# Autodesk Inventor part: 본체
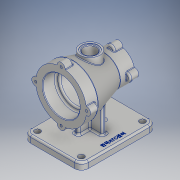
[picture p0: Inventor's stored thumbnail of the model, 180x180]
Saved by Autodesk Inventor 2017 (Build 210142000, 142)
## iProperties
Part Number: 본체
Material: 알루미늄 6061
Document SubType Name: Modeling
Designer: 222
Density: 2.7 g/cm^3
Appearance: 알루미늄 - 평지
Mass: 1029.94 g
Surface Area: 851.12 cm^2
Volume: 381.46 cm^3
Author: 222
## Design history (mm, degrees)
sketch "스케치1"
  geometry: L1 (-50, 0)-(50, 0); L2 (-50, 0)-(-50, 44); L3 (-50, 44)-(-30, 44); L4 (-30, 44)-(25, 27.5); L5 (25, 27.5)-(50, 27.5); L6 (50, 27.5)-(50, 0); 2 further points
  constraints: 12 end point, 2 horizontal, 2 perpendicular, 1 coincident, 1 midpoint, 1 vertical
  dimensions: "d0" = 100 distance of L1.start L1.end; "d1" = 88 diameter of L3 L1; "d2" = 55 diameter of L5 L1; "d3" = 20 distance of L2.end L3.end; "d5" = 25 distance of L4.end L5.end
revolve "회전1" sketch "스케치1" stored, may be unused: angle "d6" = 90 deg
node "작업 평면2"
sketch "스케치2"
  geometry: L1 (65, 50)-(-65, 50); L2 (-65, 50)-(-65, -50); L3 (-65, -50)-(65, -50); L4 (65, -50)-(65, 50); L5 (65, 50)-(-65, -50); L6 (-65, 50)-(65, -50); 1 further point
  constraints: 12 end point, 2 midpoint, 2 parallel, 1 horizontal, 1 perpendicular
  dimensions: "d8" = 130 distance of L2.end L3.end; "d9" = 100 distance of L1.end L2.end
extrude "돌출1" join sketch "스케치2" distance "d10" = 12; taper "d11" = 0 deg
fillet "모깎기1" dims "d12" = 12
sketch "스케치3"
  geometry: A1 r 12 centre (-53, 38) between (-53, 50) and (-65, 38) reference; A2 r 12 centre (53, 38) between (65, 38) and (53, 50) reference; A3 r 12 centre (53, -38) between (53, -50) and (65, -38) reference; A4 r 12 centre (-53, -38) between (-65, -38) and (-53, -50) reference; 1 further point
hole "구멍1" sketch "스케치3" at (-53, 38), (-53, -38), (53, -38), (53, 38) diameter "d13" = 10; stored, may be unused: countersink angle "d17" = 90 deg, drill point angle "d19" = 118 deg; dims "d14" = 6, "d15" = 4, "d16" = 2, "d18" = 8
node "작업 평면3"
sketch "스케치4"
  geometry: C1 r 17 at (0, 0); 1 further point
  constraints: 1 centre point, 1 coincident
  dimensions: "d21" = 34 diameter of C1
extrude "돌출2" join sketch "스케치4" stored distance "d22" = 12; taper "d23" = 0 deg
sketch "스케치11"
  geometry: L1 (-24, -4)-(24, -4); L2 (24, -4)-(24, 4); L3 (24, 4)-(-24, 4); L4 (-24, 4)-(-24, -4); L5 (-24, -4)-(24, 4); L6 (24, -4)-(-24, 4); L7 (-4, -25)-(4, -25); L8 (4, -25)-(4, 25); L9 (4, 25)-(-4, 25); L10 (-4, 25)-(-4, -25); L11 (-4, -25)-(4, 25); L12 (4, -25)-(-4, 25); 1 further point
  constraints: 24 end point, 4 midpoint, 4 parallel, 2 horizontal, 2 perpendicular
  dimensions: "d45" = 8 distance of L1.end L2.end; "d46" = 8 distance of L8.end L9.end; "d47" = 50 distance of L7.end L8.end; "d48" = 48 distance of L2.end L3.end
extrude "돌출8" join sketch "스케치11" stored distance "d49" = 33.5; taper "d50" = 0 deg
sketch "스케치12"
  geometry: C1 r 32 at (0, 0); 1 further point
  constraints: 1 centre point, 1 coincident
  dimensions: "d51" = 64 diameter of C1
extrude "돌출9" cut sketch "스케치12" distance "d52" = 23; taper "d53" = 0 deg
sketch "스케치13"
  geometry: C1 r 26 at (0, 0); 1 further point
  constraints: 1 centre point, 1 coincident
  dimensions: "d54" = 52 diameter of C1
extrude "돌출10" cut sketch "스케치13" distance "d55" = 47; taper "d56" = 0 deg
sketch "스케치14"
  geometry: C1 r 20 at (0, 0); 1 further point
  constraints: 1 centre point, 1 coincident
  dimensions: "d57" = 40 diameter of C1
extrude "돌출11" cut sketch "스케치14" distance "d58" = 30; taper "d59" = 0 deg
chamfer "모따기3" distance "d60" = 1; stored, may be unused: second distance "d61" = 2, angle "d62" = 45 deg
sketch "스케치15"
  geometry: C1 r 14 at (0, 0); 1 further point
  constraints: 1 centre point, 1 coincident
  dimensions: "d63" = 28 diameter of C1
extrude "돌출12" cut sketch "스케치15" distance "d64" = 1; taper "d65" = 0 deg
sketch "스케치16"
  geometry: C1 r 11 at (0, 0); 1 further point
  constraints: 1 centre point, 1 coincident
  dimensions: "d66" = 22 diameter of C1
extrude "돌출13" cut sketch "스케치16" distance "d67" = 25; taper "d68" = 0 deg
chamfer "모따기4" distance "d69" = 1; stored, may be unused: second distance "d70" = 2, angle "d71" = 45 deg
sketch "스케치17"
  geometry: L1 (-14, 44)-(14, 44) reference; A1 r 44 centre (0, 0) between (-6.978, 43.443) and (6.978, 43.443) reference; A2 r 7 centre (0, 44) between (6.978, 43.443) and (-6.978, 43.443); 2 further points
  constraints: 4 point on circle, 1 centre point, 1 coincident, 1 midpoint, 1 vertical alignment
  dimensions: "d72" = 14 diameter of A2
extrude "돌출14" join sketch "스케치17" distance "d73" = 15; taper "d74" = 0 deg
sketch "스케치18"
  geometry: A1 r 7 centre (0, 0) between (6.978, -0.557) and (-6.978, -0.557) reference; 1 further point
hole "구멍2" sketch "스케치18" at (0, 0) diameter "d75" = 4.134; stored, may be unused: countersink angle "d79" = 90 deg, drill point angle "d81" = 118 deg; dims "d76" = 9, "d77" = 4, "d78" = 2, "d80" = 11
sketch "스케치19"
  geometry: A1 r 27.5 centre (0, 0) between (0, 27.5) and (-6.943, 26.609) reference; A2 r 7 centre (0, 27.5) between (6.943, 26.609) and (-6.943, 26.609); 2 further points
  constraints: 5 point on circle, 2 vertical alignment, 1 centre point, 1 coincident, 1 other
  dimensions: "d85" = 14 diameter of A2
extrude "돌출15" join sketch "스케치19" distance "d86" = 15; taper "d87" = 0 deg
sketch "스케치20"
  geometry: A1 r 7 centre (0, 0) between (6.943, -0.891) and (-6.943, -0.891) reference; 1 further point
hole "구멍3" sketch "스케치20" at (0, 0) diameter "d88" = 4.134; stored, may be unused: countersink angle "d92" = 90 deg, drill point angle "d94" = 118 deg; dims "d89" = 9, "d90" = 4, "d91" = 2, "d93" = 11
fillet "모깎기3" dims "d99" = 3
fillet "모깎기4" dims "d100" = 3
fillet "모깎기5" dims "d101" = 1
fillet "모깎기6" dims "d102" = 1
fillet "모깎기7" dims "d103" = 3
fillet "모깎기8" dims "d104" = 3
fillet "모깎기9" dims "d105" = 3
node "작업 평면4"
sketch "스케치21"
  geometry: L1 (-53, -50)-(53, -50) reference; 2 further points
  constraints: 1 vertical alignment, 1 other
  dimensions: "d107" = 10 distance from line of L1 point (0, -40)
feature "엠보싱1" sketch "스케치21" dims "d12" = 12, "d108" = 0.5, "d109" = 0
fillet "모깎기10" dims "d110" = 3
fillet "모깎기11" dims "d111" = 3
fillet "모깎기12" dims "d112" = 1
fillet "모깎기13" dims "d113" = 3
fillet "모깎기14" dims "d114" = 3
node "솔리드1"
pattern_circular "원형 패턴1" dims angle "d83" = 360 deg
pattern_circular "원형 패턴2" dims angle "d96" = 360 deg
other parameters: "d7" = -82, "d20" = 45, "d106" = 27
